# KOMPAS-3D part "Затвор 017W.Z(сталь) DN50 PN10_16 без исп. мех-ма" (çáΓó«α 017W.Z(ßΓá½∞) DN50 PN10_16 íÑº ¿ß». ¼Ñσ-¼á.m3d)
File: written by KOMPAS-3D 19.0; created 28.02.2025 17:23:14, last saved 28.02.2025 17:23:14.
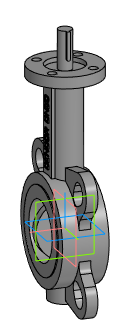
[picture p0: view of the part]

Document properties: Автор: Евгений; Полное имя файла: E:\Dendor Работа Сачек\3D для проекитирвщиков\1.5 Тип 017W.Z Сталь Затвор дисковый поворотный Межфланцевый\stp_Тип 017W.Z(сталь). Затвор без исполн. механизма\Затвор 017W.Z(сталь) DN50 PN10_16 без исп. мех-ма.m3d

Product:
- Part/product: Затвор 017W.Z(сталь) DN50 PN10_16 без исп. мех-ма

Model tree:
1. Операция без истории:1  (labels: Затвор 017W.Z(сталь) DN50 PN10_16 без исп. мех-ма)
